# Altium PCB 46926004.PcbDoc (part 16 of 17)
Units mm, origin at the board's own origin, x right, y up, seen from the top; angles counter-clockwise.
Board outline 250 x 200 mm, 6 copper layers (Top Layer, INT1_GND, INT2_SIG, INT3_SIG, INT4_GND, Bottom Layer), stack 1.71 mm thick; 1450 components, 1293 nets, 5656 pads, 2307 vias.
Unrouted connection lines stored in the file: 2.
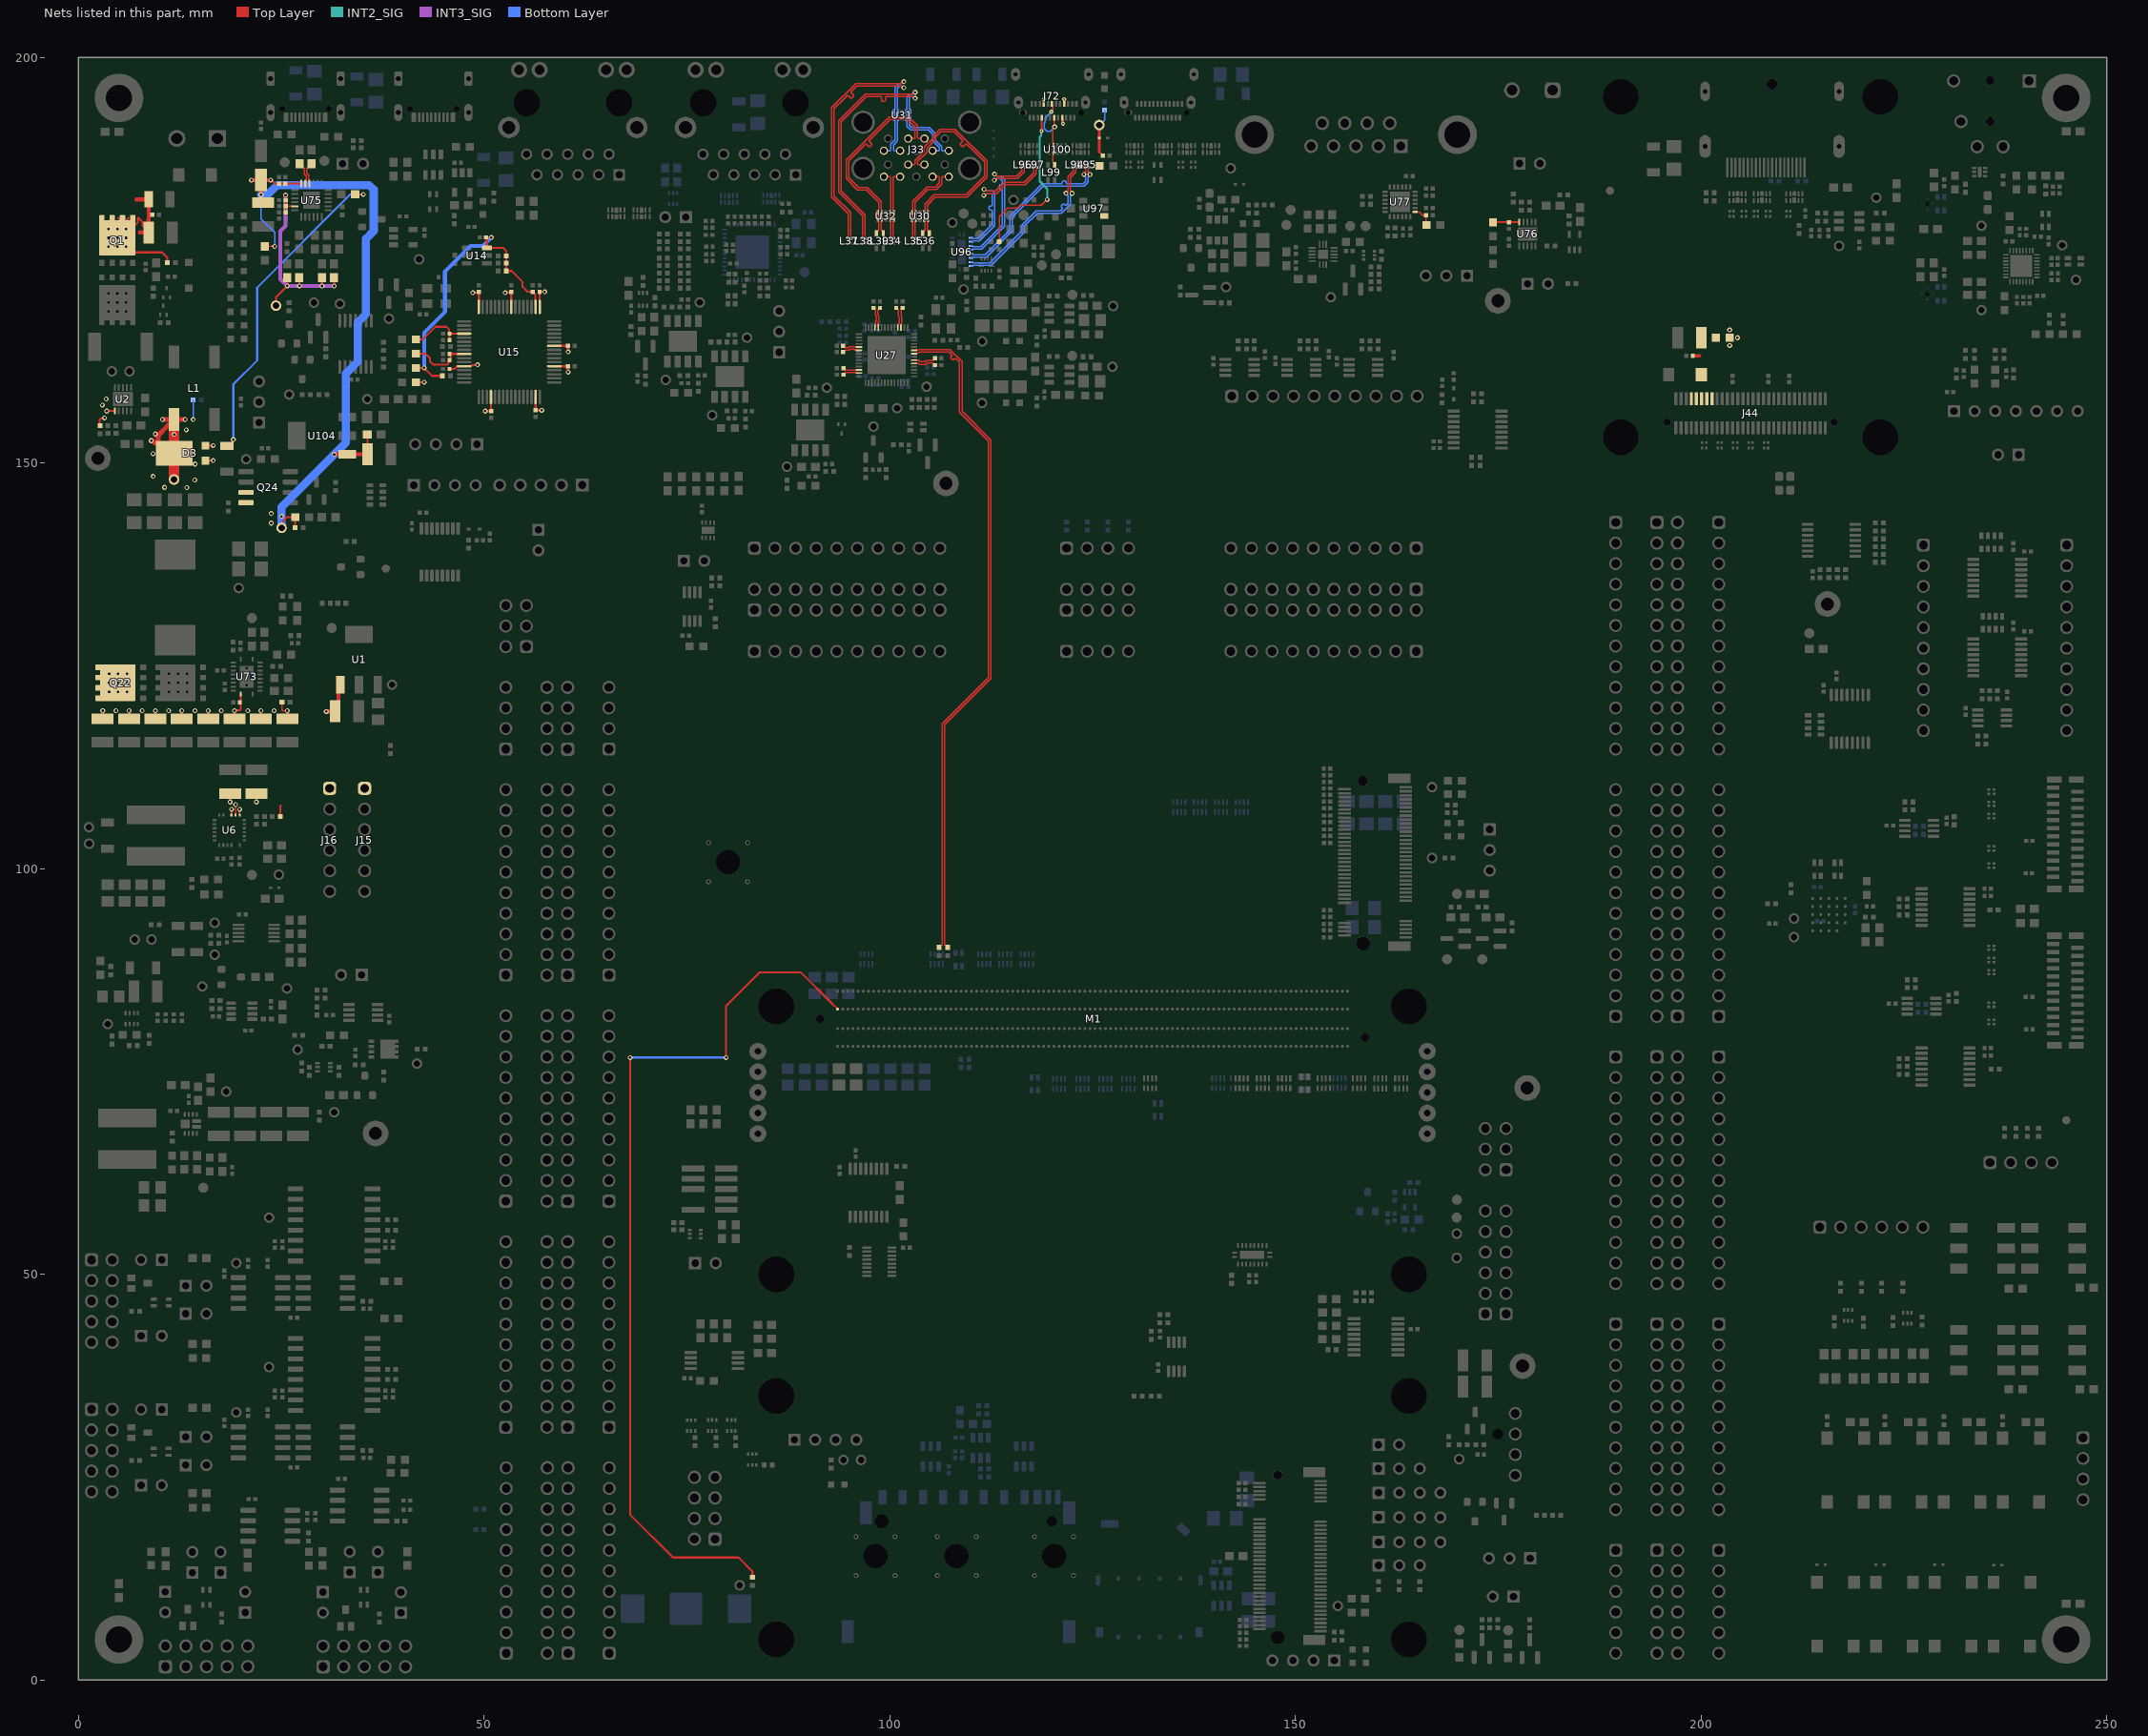
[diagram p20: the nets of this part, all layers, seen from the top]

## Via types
v1: diameter 0.6, hole 0.3, Top Layer to Bottom Layer, tented both sides, 2171 vias
v2: diameter 0.6, hole 0.3, Top Layer to Bottom Layer, 48 vias
v3: diameter 1, hole 0.5, Top Layer to Bottom Layer, tented both sides, 37 vias
v4: diameter 0.5, hole 0.2, Top Layer to Bottom Layer, tented both sides, 34 vias
v5: diameter 0.6, hole 0.3, Top Layer to Bottom Layer, tented bottom, 17 vias

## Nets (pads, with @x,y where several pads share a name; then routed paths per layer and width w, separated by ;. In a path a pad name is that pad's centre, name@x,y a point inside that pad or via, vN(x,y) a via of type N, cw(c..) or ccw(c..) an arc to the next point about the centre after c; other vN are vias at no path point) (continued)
USB_3_P: J72.A6 J72.B6 L99.1 U100.4 U100.7 | length 11.4
  Top Layer w0.15: v4(119.917,193.3) 119.917,193.362 120.117,193.563 120.117,193.87 120.075,193.912 120.075,194.175 J72.B6@120,194.25 ; J72.A6@120.25,192.55 120.25,191.527 v1(120.332,191.445) 120.332,191.357 120.107,191.132 120.107,190.038 120.075,190.006 120.075,189.405 120.175,189.305 120.175,188.93 120.075,188.829 120.075,188.571 120.175,188.471 U100.7@120.175,188.283 120.175,188.096 120.075,187.995 120.075,187.262 120.075,187.138 120.163,187.05 120.225,187.05 120.35,186.925 L99.1@120.35,186.75
  Bottom Layer w0.15: v4(119.917,193.3) 119.183,192.565 119.183,192.075 119.025,191.917 119.025,191.589 119.057,191.556 119.057,191.228 119.365,190.92 119.807,190.92 v1(120.332,191.445)
USB_3_SSRX1_N: L95.1 U96.16 | length 21.4
  Top Layer w0.15: v1(123.93,185.587) 123.93,185.68 124.15,185.9 124.15,186.287 124.125,186.312 124.125,186.4 L95.1@124.05,186.475
  Bottom Layer w0.15: U96.16@110.01,175.775 110.19,175.775 110.29,175.675 111.775,175.675 114.821,178.722 114.821,180.437 118.806,184.422 121.076,184.422 121.151,184.422 121.251,184.522 121.251,184.69 121.351,184.79 121.651,184.79 121.751,184.69 121.751,184.522 121.851,184.422 122.627,184.422 123.827,184.422 124.153,184.748 124.153,185.274 123.93,185.497 v1(123.93,185.587)
USB_3_SSRX1_P: L95.2 U96.17 | length 21.4
  Top Layer w0.15: L95.2@124.55,186.475 124.475,186.4 124.475,186.312 124.45,186.287 124.45,185.895 124.68,185.665 v1(124.68,185.575)
  Bottom Layer w0.15: U96.17@110.01,175.275 110.19,175.275 110.29,175.375 111.899,175.375 115.121,178.597 115.121,180.313 118.93,184.122 123.951,184.122 124.453,184.624 124.453,185.262 124.68,185.489 v1(124.68,185.575)
USB_3_SSRX2_N: L97.2 U96.12 | length 17.2
  Top Layer w0.15: v1(111.6,183) 111.69,183 111.913,183.223 113.181,183.223 114.259,184.301 116.714,184.301 118.05,185.637 118.05,186.287 118.075,186.312 118.075,186.4 L97.2@118.15,186.475
  Bottom Layer w0.15: U96.12@110.01,177.775 110.19,177.775 110.275,177.69 110.898,177.69 112.616,179.407 112.616,180.997 112.616,181.072 112.516,181.172 112.311,181.172 112.211,181.272 112.211,181.572 112.311,181.672 112.516,181.672 112.616,181.772 112.616,182.03 112.616,183.122 112.528,183.21 111.913,183.21 111.703,183 v1(111.6,183)
USB_3_SSRX2_P: L97.1 U96.13 | length 17.2
  Top Layer w0.15: v1(111.612,183.75) 111.698,183.75 111.925,183.523 113.057,183.523 114.135,184.601 116.59,184.601 117.75,185.761 117.75,186.287 117.725,186.312 117.725,186.4 L97.1@117.65,186.475
  Bottom Layer w0.15: U96.13@110.01,177.275 110.19,177.275 110.275,177.36 111.035,177.36 112.946,179.271 112.946,183.259 112.664,183.54 111.925,183.54 111.715,183.75 v1(111.612,183.75)
USB_3_SSTX1_N: L94.1 U96.18 | length 21.3
  Top Layer w0.15: v1(121.723,183.271) 121.723,183.359 121.948,183.584 121.948,185.305 122.625,185.982 122.625,186.287 122.6,186.312 122.6,186.4 L94.1@122.525,186.475
  Bottom Layer w0.15: U96.18@110.01,174.775 110.19,174.775 110.29,174.675 112.361,174.675 116.273,178.587 116.273,179.307 118.067,181.1 121.041,181.1 121.192,181.251 121.245,181.304 121.245,181.446 121.126,181.565 121.126,181.706 121.338,181.918 121.479,181.918 121.599,181.799 121.74,181.799 121.821,181.88 121.946,182.005 121.946,182.958 121.723,183.181 v1(121.723,183.271) 121.723,183.168 121.933,182.958
USB_3_SSTX1_P: L94.2 U96.19 | length 21.3
  Top Layer w0.15: v1(122.473,183.259) 122.473,183.347 122.248,183.572 122.248,185.181 122.925,185.858 122.925,186.287 122.95,186.312 122.95,186.4 L94.2@123.025,186.475
  Bottom Layer w0.15: U96.19@110.01,174.275 110.19,174.275 110.29,174.375 112.486,174.375 116.573,178.463 116.573,179.183 118.191,180.8 121.165,180.8 122.246,181.881 122.246,182.946 122.473,183.173 v1(122.473,183.259) 122.473,183.156 122.263,182.946
USB_3_SSTX2_N: L96.2 U96.14 | length 16.8
  Top Layer w0.15: v1(112.89,184.87) 112.98,184.87 113.203,185.093 115.742,185.093 116.55,185.901 116.55,186.287 116.575,186.312 116.575,186.4 L96.2@116.65,186.475
  Bottom Layer w0.15: U96.14@110.01,176.775 110.19,176.775 110.29,176.675 111.203,176.675 113.842,179.314 113.842,183.63 113.842,183.705 113.742,183.805 113.587,183.805 113.487,183.905 113.487,184.205 113.587,184.305 113.742,184.305 113.842,184.405 113.842,184.69 113.842,184.8 113.55,185.093 113.203,185.093 112.98,184.87 v1(112.89,184.87)
USB_3_SSTX2_P: L96.1 U96.15 | length 16.8
  Top Layer w0.15: v1(112.902,185.62) 112.988,185.62 113.215,185.393 115.618,185.393 116.25,186.025 116.25,186.287 116.225,186.312 116.225,186.4 L96.1@116.15,186.475
  Bottom Layer w0.15: U96.15@110.01,176.275 110.19,176.275 110.29,176.375 111.327,176.375 114.142,179.19 114.142,184.924 113.674,185.393 113.215,185.393 112.988,185.62 v1(112.902,185.62)
USB_3_VBUS: C35.2 C328.2 D36.2 J72.A4 J72.A9 J72.B4 J72.B9 R389.2 R396.2 U97.1 X107.1 | length 28.5
  Top Layer w0.15: R389.2@113.495,177.305 113.495,180.373 114.039,180.918 114.537,181.416 115.719,181.416 116.085,181.782 118.699,181.782 v1(119.4,182.483) ; 125.825,188.36 C328.2@126.285,187.9
  Top Layer w0.25: v4(118.701,190.913) 118.725,190.938 118.725,192.525 J72.A9@118.75,192.55 ; J72.A4@121.25,192.55 121.275,192.525 121.275,191.959 121.35,191.884 v4(121.35,191.817)
  Top Layer w0.3: J72.B4@119,194.25 v4(119,194.85) ; J72.B9@121.5,194.25 v4(121.5,194.85)
  Top Layer w0.4: 125.825,188.36 X107.1@125.825,191.662
  INT2_SIG w0.25: v4(118.701,190.913) 118.653,190.866 118.653,190.347 118.47,190.163 118.47,184.746 119.4,183.815 v1(119.4,182.483)
  Bottom Layer w0.15: X107.1@125.825,191.662 126.482,192.319 R396.2@126.482,193.5
USB_4_N: J33.U2 L36.4 U30.4 U30.7 | length 28.4
  Top Layer w0.15: L36.4@104.05,178.275 104.05,178.45 104.325,178.725 104.325,179.371 104.325,179.746 104.225,179.846 U30.4@104.225,180.033 104.225,180.221 104.325,180.321 104.325,180.579 104.225,180.679 U30.7@104.225,180.867 104.225,181.054 104.325,181.154 104.325,181.924 105.476,183.075 109.375,183.075 111.675,185.375 111.675,187.111 110.253,188.533 109.487,189.298 109.346,189.298 109.053,189.006 108.912,189.006 108.7,189.218 108.7,189.359 108.993,189.652 108.993,189.793 108.586,190.2 107.936,190.85 106.275,190.85 105.625,190.2 105.625,189.87 104.555,188.8 104.555,188.325 103.43,187.2 103.43,186.888 103.518,186.8 J33.U2@104.28,186.8
USB_4_P: J33.U3 L36.1 U30.5 U30.6 | length 28.4
  Top Layer w0.15: J33.U3@102.28,186.8 103.042,186.8 103.13,186.888 103.13,187.325 104.255,188.45 104.255,188.925 105.325,189.995 105.325,190.324 106.151,191.15 108.06,191.15 111.975,187.235 111.975,185.25 109.499,182.775 105.6,182.775 104.625,181.8 104.625,181.155 104.725,181.054 U30.6@104.725,180.867 104.725,180.679 104.625,180.579 104.625,180.321 104.725,180.221 U30.5@104.725,180.033 104.725,179.846 104.625,179.745 104.625,179.495 104.625,178.725 104.9,178.45 L36.1@104.9,178.275
USB_4_SSRX_N: J33.U5 L34.2 U32.2 U32.9 | length 8.6
  Top Layer w0.15: J33.U5@99.28,185.3 100.042,185.3 100.13,185.212 100.13,181.171 100.03,181.071 U32.2@100.03,180.884 100.03,180.696 100.13,180.596 100.13,180.338 100.03,180.238 U32.9@100.03,180.05 100.03,179.863 100.13,179.763 100.13,177.913 100.105,177.888 100.105,177.8 L34.2@100.03,177.725
USB_4_SSRX_P: J33.U6 L34.1 U32.1 U32.10 | length 8.6
  Top Layer w0.15: L34.1@100.53,177.725 100.455,177.8 100.455,177.888 100.43,177.913 100.43,179.763 100.53,179.863 U32.10@100.53,180.05 100.53,180.238 100.43,180.338 100.43,180.596 100.53,180.696 U32.1@100.53,180.884 100.53,181.071 100.43,181.171 100.43,182.1 100.43,185.212 100.518,185.3 J33.U6@101.28,185.3
USB_4_SSTX_N: J33.U8 L35.2 U30.1 U30.10 | length 10.6
  Top Layer w0.15: L35.2@102.725,177.725 102.8,177.8 102.8,177.888 102.825,177.913 102.825,179.746 102.725,179.846 U30.1@102.725,180.033 102.725,180.221 102.825,180.321 102.825,180.579 102.737,180.667 U30.10@102.737,181.067 ; U30.10@102.725,181.054 102.825,181.154 102.825,182.243 104.582,184 105.613,184 106.13,184.517 106.13,185.212 106.042,185.3 J33.U8@105.28,185.3
USB_4_SSTX_P: J33.U9 L35.1 U30.2 U30.9 | length 10.6
  Top Layer w0.15: L35.1@103.225,177.725 103.15,177.8 103.15,177.888 103.125,177.913 103.125,179.746 103.225,179.846 U30.2@103.225,180.033 103.225,180.221 103.125,180.321 103.125,180.579 103.225,180.679 U30.9@103.225,180.867 103.225,181.054 103.125,181.154 103.125,182.119 104.706,183.7 105.737,183.7 106.43,184.393 106.43,185.212 106.518,185.3 J33.U9@107.28,185.3
USB_5_N: J33.L2 L39.4 U32.5 U32.6 | length 25.5
  Top Layer w0.15: L39.4@98.355,178.325 98.355,178.5 98.48,178.625 98.542,178.625 98.63,178.713 98.63,179.388 ; 98.63,179.388 98.63,179.763 98.53,179.863 U32.6@98.53,180.05 98.53,180.238 98.63,180.338 98.63,180.596 98.53,180.696 U32.5@98.53,180.884 98.53,181.071 98.63,181.171 98.63,181.546 ; 98.63,181.546 98.63,182.133 97.096,183.667 96.034,183.667 94.625,185.076 94.625,187.349 99.951,192.675 102.324,192.675 103.43,191.569 103.43,190.088 103.518,190 J33.L2@104.28,190
USB_5_P: J33.L3 L39.1 U32.4 U32.7 | length 25.5
  Top Layer w0.15: L39.1@99.205,178.325 99.205,178.5 99.08,178.625 99.018,178.625 98.93,178.713 98.93,179.512 98.93,179.762 99.03,179.863 U32.7@99.03,180.05 99.03,180.238 98.93,180.338 98.93,180.596 99.03,180.696 U32.4@99.03,180.884 99.03,181.071 98.93,181.172 98.93,181.422 98.93,182.257 97.22,183.967 96.158,183.967 94.925,185.2 94.925,187.225 96.597,188.897 97.003,189.303 97.145,189.303 97.438,189.011 97.579,189.011 97.791,189.223 97.791,189.364 97.498,189.657 97.498,189.798 97.992,190.292 100.075,192.375 102.2,192.375 103.13,191.445 103.13,190.088 103.042,190 J33.L3@102.28,190
USB_5_SSRX_N: J33.L5 L37.2 U31.1 U31.10 | length 38
  Top Layer w0.15: L37.2@94.775,177.725 94.85,177.8 94.85,177.888 94.875,177.913 94.875,180.75 92.85,182.775 92.85,193.814 95.826,196.79 101.437,196.79 101.662,197.015 v1(101.75,197.015)
  Bottom Layer w0.15: J33.L5@99.28,188.5 100.046,188.5 100.134,188.588 100.134,189.328 100.625,189.82 100.625,192.204 100.525,192.304 U31.10@100.525,192.491 100.525,192.679 100.625,192.779 100.625,193.038 100.525,193.138 U31.1@100.525,193.325 100.525,193.513 100.625,193.613 100.625,196.307 101.108,196.79 101.437,196.79 101.662,197.015 v1(101.75,197.015) 101.647,197.015 101.437,196.805
USB_5_SSRX_P: J33.L6 L37.1 U31.2 U31.9 | length 37.9
  Top Layer w0.15: L37.1@95.275,177.725 95.2,177.8 95.2,177.888 95.175,177.913 95.175,180.874 93.15,182.899 93.15,193.69 94.354,194.894 94.76,195.3 94.902,195.3 95.197,195.005 95.338,195.005 95.55,195.217 95.55,195.359 95.255,195.654 95.255,195.795 95.837,196.377 95.95,196.49 101.437,196.49 101.662,196.265 v1(101.75,196.265)
  Bottom Layer w0.15: U31.9@100.975,192.491 100.975,192.729 100.925,192.779 100.925,193.038 101.025,193.138 U31.2@101.025,193.325 101.025,193.513 100.925,193.613 100.925,196.182 101.233,196.49 101.437,196.49 101.662,196.265 v1(101.75,196.265) 101.647,196.265 101.437,196.475 ; U31.9@101.025,192.491 101.025,192.304 100.925,192.204 100.925,189.695 100.445,189.215 100.445,188.605 100.55,188.5 J33.L6@101.28,188.5
USB_5_SSTX_N: J33.L8 L38.2 U31.4 U31.7 | length 39
  Top Layer w0.15: L38.2@96.55,177.725 96.625,177.8 96.625,177.888 96.65,177.913 96.65,180.475 93.7,183.425 93.7,192.206 96.984,195.49 102.812,195.49 103.037,195.715 v1(103.125,195.715)
  Bottom Layer w0.15: U31.7@102.11,192.764 U31.7@102.025,192.679 ; 102.546,191.075 102.443,191.178 ; 102.812,195.505 103.022,195.715 v1(103.125,195.715) 103.037,195.715 102.812,195.49 102.483,195.49 102.125,195.132 102.125,193.613 102.025,193.513 U31.4@102.025,193.325 102.025,193.138 102.125,193.038 102.125,192.779 U31.7@102.025,192.679 ; J33.L8@105.28,188.5 106.022,188.5 106.11,188.588 106.11,188.912 105.29,189.731 105.29,190.531 104.731,191.09 102.531,191.09 102.443,191.178 ; U31.7@102.025,192.679 U31.7@102.025,192.491 102.025,192.304 102.125,192.204 102.125,191.496 102.443,191.178
USB_5_SSTX_P: J33.L9 L38.1 U31.5 U31.6 | length 38.8
  Top Layer w0.15: L38.1@97.05,177.725 96.975,177.8 96.975,177.888 96.95,177.913 96.95,180.599 94,183.549 94,192.082 97.108,195.19 98.299,195.19 98.874,195.19 98.974,195.09 98.974,194.668 99.074,194.568 99.374,194.568 99.474,194.668 99.474,195.09 99.574,195.19 100.38,195.19 102.812,195.19 103.037,194.965 v1(103.125,194.965)
  Bottom Layer w0.15: 102.812,195.175 103.022,194.965 v1(103.125,194.965) 103.037,194.965 102.812,195.19 102.608,195.19 102.425,195.008 102.425,193.613 102.525,193.513 U31.5@102.525,193.325 102.525,193.138 102.425,193.037 102.425,192.779 102.525,192.679 U31.6@102.525,192.491 102.525,192.304 102.425,192.203 102.425,191.65 102.685,191.39 104.855,191.39 105.59,190.655 105.59,189.856 106.41,189.036 106.41,188.588 106.498,188.5 J33.L9@107.28,188.5
USB__2__SSRX_N: C120.2 U27.48 | length 2.8
  Top Layer w0.15: U27.48@102.995,162.693 103.022,162.666 103.547,162.666 103.723,162.49 104.329,162.49 104.483,162.644 105.272,162.644 C120.2@105.567,162.939
USB__2__SSRX_P: C117.2 U27.47 | length 2.8
  Top Layer w0.15: U27.47@102.995,162.293 103.022,162.266 103.523,162.266 103.598,162.19 104.454,162.19 104.607,162.344 105.299,162.344 C117.2@105.567,162.075
USB__2__SSTX_N: R462.2 U27.51 | length 82.8
  Top Layer w0.15: U27.51@102.995,163.893 103.01,163.907 103.461,163.907 103.553,164 107.42,164 108.902,162.518 108.902,156.389 112.45,152.84 112.45,123.45 106.76,117.76 106.76,90.613 106.848,90.525 106.91,90.525 R462.2@107.135,90.3
USB__2__SSTX_P: R461.2 U27.50 | length 82.8
  Top Layer w0.15: U27.50@102.995,163.493 103.297,163.493 103.37,163.566 103.543,163.566 103.677,163.7 107.218,163.7 107.296,163.7 107.663,163.332 107.663,163.191 107.546,163.074 107.546,162.932 107.758,162.72 107.9,162.72 108.017,162.837 108.158,162.837 108.502,162.493 108.602,162.394 108.602,156.264 112.15,152.716 112.15,123.574 106.46,117.885 106.46,90.613 106.373,90.525 106.31,90.525 R461.2@106.085,90.3
USB__3__SSTX_N: C131.2 U27.4 | length 2.7
  Top Layer w0.15: C131.2@100.792,169.125 101.082,168.835 101.082,168.062 101.194,167.95 101.194,167.312 101.167,167.285 101.167,167.278 101.067,167.178 101.067,167.069 100.994,166.996 U27.4@100.994,166.694
USB__3__SSTX_P: C135.2 U27.3 | length 2.6
  Top Layer w0.15: U27.3@101.394,166.694 101.421,166.721 101.421,167.107 101.467,167.153 101.467,167.161 101.494,167.188 101.494,168.074 101.382,168.186 101.382,168.772 101.382,168.94 C135.2@101.567,169.125
USB__4__SSTX_N: C132.2 U27.11 | length 2.7
  Top Layer w0.15: C132.2@97.992,169.125 98.242,168.875 98.242,168.227 98.36,168.109 98.36,167.563 98.244,167.447 98.244,167.1 98.221,167.077 98.221,166.721 U27.11@98.194,166.694
USB__4__SSTX_P: C136.2 U27.10 | length 2.7
  Top Layer w0.15: U27.10@98.594,166.694 98.567,166.721 98.567,167.077 98.544,167.1 98.544,167.323 98.66,167.439 98.66,168.233 98.542,168.351 98.542,168.875 C136.2@98.792,169.125
USB__5__SSTX_N: C133.2 U27.20 | length 2.1
  Top Layer w0.15: C133.2@94.367,163.7 94.367,163.8 94.452,163.885 94.517,163.885 94.54,163.908 95.008,163.908 95.118,164.018 95.619,164.018 95.721,163.915 96.17,163.915 U27.20@96.193,163.893
USB__5__SSTX_P: C137.2 U27.19 | length 2
  Top Layer w0.15: C137.2@94.367,164.45 94.367,164.35 94.452,164.265 94.517,164.265 94.54,164.242 94.869,164.242 94.979,164.352 95.73,164.352 95.762,164.32 96.166,164.32 U27.19@96.193,164.293
USB__6__SSTX_N: C134.2 U27.27 | length 2
  Top Layer w0.15: C134.2@94.292,160.897 94.542,161.147 95.358,161.147 95.363,161.143 95.787,161.143 95.81,161.12 96.166,161.12 U27.27@96.193,161.093
USB__6__SSTX_P: C138.2 U27.26 | length 2
  Top Layer w0.15: C138.2@94.292,161.697 94.542,161.447 95.483,161.447 95.487,161.443 95.787,161.443 95.81,161.466 96.166,161.466 U27.26@96.193,161.493
USB_CYP_N: R321.1 U75.16 | length 2.9
  Top Layer w0.15: U75.16@28.475,184.45 28.475,184.775 28.375,184.875 28.375,185.475 28.15,185.7 28.15,186.337 28.238,186.425 28.325,186.425 28.75,186.85 R321.1@28.75,186.9
USB_CYP_P: R320.1 U75.17 | length 2.9
  Top Layer w0.15: R320.1@27.25,186.9 27.25,186.85 27.675,186.425 27.762,186.425 27.85,186.337 27.85,185.576 28.075,185.351 28.075,184.875 27.975,184.775 U75.17@27.975,184.45
V232: C306.1 L79.2 U77.19 | length 2.8
  Top Layer w0.15: U77.19@164.725,180.95 U77.19@164.915,180.95 165.243,180.95 165.31,180.884 165.643,180.55 C306.1@166.1,180.55 166.1,179.425 L79.2@166.175,179.35
V485: C308.1 L80.2 U76.10 | length 3.2
  Top Layer w0.25: L80.2@174.373,179.65 174.402,179.679 C308.1@176.3,179.679 U76.10@177.6,179.679
V+: C2.2 C3.1 F1.2 Q1.5 Q1.6 Q1.7 Q1.8 R5.2 R351.2 U2.1 | length 22.4
  Top Layer w0.25: R5.2@2.676,154.627 2.604,154.699 2.604,155.356 2.751,155.503 3.142,155.503 v1(3.209,155.57) ; U2.1@4.475,156.445 4.477,156.443 U2.1@4.477,156.438 ; 4.89,180.23 4.89,180.192 5.538,179.544 5.538,179.217 5.605,179.15 5.672,179.217 5.672,179.681 6.16,180.169 6.16,180.23 ; Q1.8@5.995,176.76 6.78,175.975 10.32,175.975 10.95,175.345 R351.2@10.95,174.72 ; Q1.8@6.8,179.15 7.333,179.683 7.333,180.133 7.43,180.23 ; 7.43,180.192 7.43,180.169 7.928,179.671 7.928,179.217 7.995,179.15 8.515,179.67 8.515,180.045 8.673,180.203 8.7,180.23
  Top Layer w0.254: v1(3.5,156.4) 3.545,156.445 4.142,156.445 ; 3.809,156.445 4.142,156.445 ; U2.1@4.475,156.445 4.142,156.445
  Top Layer w0.5: 7.15,182.5 F1.2@8.673,182.5 8.673,180.203 C2.2@8.673,178.427 ; 7.55,178.45 8.65,178.45 C2.2@8.673,178.427 ; C2.2@8.675,178.425 C2.2@8.673,178.427
  other v1: 2.95,157.15 3.425,157.9
V_BUS_PD: C284.2 C293.2 C296.2 C297.2 C299.1 L77.2 Q24.7 Q24.8 R315.2 R325.1 R332.2 U75.18 U104.1 X94.1 | length 87.9
  Top Layer w0.15: R315.2@22.995,176.703 v1(24.192,176.703)
  Top Layer w0.25: L77.2@22.5,184.89 L77.2@22.51,184.88 ; v1(23.7,184.875) 23.795,184.875 24.22,184.45 C297.2@24.725,184.45 C296.2@25.525,184.45 U75.18@27.475,184.45 ; X94.1@25.045,142.015 25.246,142.216 25.246,142.891 25.685,143.33 C299.1@26.71,143.33 R332.2@26.71,142.03 ; C284.2@35.625,151.075 R325.1@35.625,153.566
  Top Layer w0.5: v1(21.32,184.88) 22.51,184.88 22.5,184.87 v1(22.5,183.08) ; L77.2@22.51,184.875 v1(23.7,184.875) ; v1(31.525,151.075) U104.1@33.125,151.075 C284.2@35.625,151.075
  Bottom Layer w0.15: v1@22.5,183.075 22.5,180.1 24.192,178.408 v1(24.192,176.703)
  Bottom Layer w1: v1@22.5,183.075 23.309,183.075 24.514,184.28 35.814,184.28 36.4,183.694 36.4,178.603 35.45,177.653 35.45,168.36 34.45,167.36 34.45,162.528 32.974,161.051 32.974,152.524 25.045,144.595 X94.1@25.045,142.015
  other v1: 23.765,142.6 25.045,143.434 23.765,143.795
VCC_BACKUP: M1.B100 R227.2 | length 110.7
  Top Layer w0.15: 92.973,83.291 92.976,83.291 M1.B100@93.567,82.7
  Top Layer w0.25: v1(68,76.726) 68,20.4 73.3,15.1 81.356,15.1 83.085,13.37 R227.2@83.085,12.521 ; v1(79.825,76.726) 79.825,83.094 83.931,87.2 89.064,87.2 92.973,83.291
  Bottom Layer w0.25: v1(68,76.726) v1(79.825,76.726)
VCC_FT: C85.2 C87.2 C88.2 C89.2 L19.2 U15.20 U15.31 U15.42 U15.56 | length 10.8
  Top Layer w0.25: L19.2@41.615,159.975 v1(42.615,159.975) ; v1(50.14,156.4) C85.2@50.865,156.4 50.865,157.371 50.86,157.377 50.86,158.13 U15.20@50.865,158.135 ; v1(52.6,170.99) 52.655,171.045 53.285,171.045 C89.2@53.34,171.1 ; U15.56@53.35,169.25 C89.2@53.35,170.99
  Top Layer w0.3: U15.31@56.35,158.15 56.35,156.515 C87.2@56.365,156.5 v1(57.115,156.5) ; U15.42@58.65,164.45 C88.2@60.35,164.45 v1(60.35,163.7)
VCORE_FT: C82.2 C83.2 C84.2 C86.2 U15.12 U15.37 U15.49 U15.64 | length 11.1
  Top Layer w0.15: C86.2@49.34,171 C86.2@49.35,170.99 ; U15.64@49.345,169.245 U15.64@49.35,169.25
  Top Layer w0.25: C83.2@45.74,161.6 46.349,161.6 46.611,161.862 46.688,161.862 46.701,161.875 46.711,161.875 46.786,161.95 U15.12@47.55,161.95 47.56,161.96 48.432,161.96 48.531,162.058 49.125,162.058 v1(49.192,162.125) ; v1(48.6,170.99) 49.35,170.99 U15.64@49.35,169.25 ; U15.49@56.85,169.25 C82.2@56.85,171.1 v1(57.475,171.1)
  Top Layer w0.3: U15.37@58.65,161.95 C84.2@60.35,161.95 v1(60.35,161.2)
VDDD_3V3: C292.2 C294.2 C295.2 R328.2 R329.1 R337.2 R388.1 U75.23 X93.1 | length 28
  Top Layer w0.15: C295.2@25.55,180.9 C294.2@25.55,181.65 C292.2@25.55,182.4 ; C294.2@25.65,181.65 U75.23@26.675,181.65
  Top Layer w0.25: X93.1@24.35,169.4 24.35,170.429 v1(25.75,171.829) 25.75,172.818 R388.1@25.72,172.848 ; v1(25.532,183.038) 25.541,183.029 25.541,182.509 C292.2@25.65,182.4 ; R337.2@27.22,172.848 27.25,172.818 v1(27.25,171.829) ; R329.1@29.995,172.845 30.025,172.815 v1(30.025,171.826) ; R328.2@31.495,172.844 31.525,172.814 v1(31.525,171.825)
  INT3_SIG w0.5: v1(25.532,183.038) 25.532,179.232 24.892,178.592 24.892,172.684 25.75,171.826 26.325,171.826 ; 26.325,171.826 v1(31.525,171.825)
VIN: C1.2 C20.2 C23.2 C265.2 C266.2 C270.1 C272.2 C273.2 C274.2 C275.2 C278.2 C281.2 D3.3 J15.1 J16.1 L1.3 L55.2 Q22.5 Q22.6 Q22.7 Q22.8 R10.1 R35.2 R307.2 U1.1 U6.7 U6.8 U6.9 U73.20 X3.1 | length 51.7
  Top Layer w0.15: Q22.8@2.422,121.015 2.627,121.22 2.992,121.22 Q22.8@3.502,121.73 ; Q22.7@2.422,122.285 2.46,122.285 3.014,122.839 3.416,122.839 Q22.8@3.502,122.925 ; Q22.6@2.422,123.555 2.937,123.555 3.502,124.12 3.002,124.62 2.627,124.62 Q22.5@2.422,124.825 ; L1.3@11.79,155.372 L1.3@11.794,155.368 ; v1(18.7,108.225) C20.2@18.7,109.275 ; U6.9@18.87,106.627 v1(18.87,107.335) ; U6.8@19.37,106.627 v1@19.37,107.9 ; U6.7@19.871,106.627 v1(19.871,107.335) ; R307.2@25.092,120.525 25.092,119.603 25.22,119.475 v1(25.742,119.475)
  Top Layer w0.25: C278.2@2.992,118.475 v1(2.992,119.475) ; C281.2@6.242,118.475 v1(6.242,119.475) ; C275.2@9.492,118.475 v1(9.492,119.475) ; C274.2@12.742,118.475 v1(12.742,119.475) ; C273.2@15.992,118.475 v1(15.992,119.475) ; v1@19.156,119.561 v1(19.242,119.475) ; C272.2@19.242,118.475 v1(19.242,119.475) ; U73.20@19.992,121.525 19.992,120.5 19.992,119.652 19.882,119.542 19.309,119.542 v1(19.242,119.475) ; C266.2@22.492,118.475 v1(22.492,119.475) ; R35.2@24.9,106.45 24.9,107.729 24.946,107.775 ; C265.2@25.742,118.475 v1(25.742,119.475)
  Top Layer w0.5: v1(30.55,119.375) 31.6,119.375 32.05,119.825 32.05,122.425 U1.1@32.3,122.675
  Top Layer w0.6: v1(8.967,152.762) v1@9.114,152.762 ; 9.353,152.523 9.85,152.523 D3.3@9.85,152.446 ; D3.3@10.277,152.02 D3.3@9.85,152.446 ; D3.3@10.315,152.058 11.15,151.222 D3.3@11.798,151.222 11.074,151.222 D3.3@9.85,152.446 ; v1(10.362,155.372) L1.3@11.779,155.372 ; v1(11.79,153.541) L1.3@11.79,155.383 ; v1(13.148,155.372) L1.3@11.779,155.372 ; D3.3@9.85,152.446 9.85,153.203 9.73,153.323 11.048,154.641 11.45,154.641 11.779,154.97 L1.3@11.779,155.372
  Top Layer w1.3: X3.1@11.794,147.972 L1.3@11.794,155.368
  Bottom Layer w0.15: v1(14.14,155.36) 14.14,157.77 R10.1@14.145,157.775
  other v1: 19.366,107.9 21.925,108.225 4.617,119.475 7.867,119.475 11.117,119.475 14.367,119.475 17.617,119.475 20.867,119.475 24.117,119.475 13.35,146.975 10.625,147 14.36,147.915 9.2,148.37 14.38,149.88 9.196,151.148 9.486,153.589 13.3,154.1 203.522,164.497 204.475,165.45 203.522,166.403
VIN_DSI: C205.2 C208.2 D31.2 J44.7 J44.9 J44.11 J44.13 J44.15 L55.1 | length 0.9
  Top Layer w0.4: C208.2@198.972,163.2 199.851,163.2
VPD: D3.1 D3.2 F2.2 R339.1 | length 42
  Top Layer w0.25: D3.1@15.684,150.302 15.689,150.307 v1(16.609,150.307) ; D3.2@15.689,152.137 15.699,152.147 v1(16.609,152.147) ; F2.2@18.305,152.13 18.605,152.13 18.975,152.5 18.975,152.667 19.1,152.792 v1(19.1,152.887) ; R339.1@34.11,183.15 34.135,183.125 v1(35.125,183.125)
  Bottom Layer w0.25: v1(19.1,152.887) 19.1,159.715 22.035,162.65 22.035,171.635 33.525,183.125 v1(35.125,183.125)
VPHY_FT: C76.2 C80.2 L16.2 U15.4 | length 7.9
  Top Layer w0.25: L16.2@41.615,165.225 42.44,165.225 44.015,166.8 45.34,166.8 45.701,166.439 45.701,166.085 C80.2@45.753,166.034 ; C76.2@45.74,165.175 C80.2@45.74,165.95 ; C80.2@45.756,166.034 45.84,165.95 U15.4@47.55,165.95
VPLL_FT: C75.2 C79.2 L18.2 U15.9 | length 7.9
  Top Layer w0.25: L18.2@41.615,163.475 42.79,163.475 43.34,162.925 43.34,162.525 43.715,162.15 45.45,162.15 45.605,162.305 45.605,162.565 C75.2@45.74,162.7 45.84,162.7 C79.2@45.84,163.45 ; C79.2@45.84,163.475 45.865,163.45 U15.9@47.55,163.45
VREG_FT: C74.2 C78.2 L17.2 R86.1 R87.1 R89.1 R90.1 U14.6 U15.50 | length 37.6
  Top Layer w0.25: L17.2@41.615,161.725 v1(42.615,161.725) 43.59,160.75 R90.1@44.84,160.75 ; v1(50.9,177.811) 50.895,177.816 50.35,177.816 50.355,177.811 U14.6@50.355,176.516 52.383,176.516 52.74,176.159 R86.1@52.74,175.55 R87.1@52.74,174.625 R89.1@52.74,173.675 53.403,173.675 54.744,172.334 54.744,171.741 55.374,171.111 55.989,171.111 55.989,171.089 56.011,171.089 56.135,170.965 56.135,170.942 56.33,170.748 56.33,170.056 56.34,170.045 56.34,169.26 U15.50@56.35,169.25
  Bottom Layer w0.5: v1(42.615,161.725) 42.615,166.065 45.195,168.645 45.195,173.631 48.327,176.763 49.852,176.763 v1(50.9,177.811)
pads on no net: B1.2 B1.4 B2.2 B2.4 B3.2 B3.4 B4.2 B4.4 B5.2 B5.4 B6.2 B6.4 B7.2 B7.4 B8.2 B8.4 D39.2 D39.4 D40.2 D40.4 D41.2 D41.4 D42.2 D42.4 D44.2 FID1.1 FID2.1 FID3.1 FID4.1 FID5.1 FID6.1 J23. J23.A8 J23.B8 J27. J30.0 J30.11 J32.0 J34.0 J34.10 J36.0 J36.10 J39. J39.56 J39.58 J39.59 J39.60 J39.61 J39.62 J39.63 J39.64 J39.65 J39.68 J39.69 J39.75 J39.P1 J39.P2 J42.C4 J42.C6 J42.C8 J43. J43.5 J43.6 J43.7 J43.8 J43.11 J43.13 J43.17 J43.19 J43.20 J43.22 J43.23 J43.24 J43.25 J43.26 J43.28 J43.30 J43.32 J43.34 J43.36 J43.46 J43.48 J43.56 J43.58 J43.67 J43.68 J43.69 J43.SH1 J43.SH2 J44. J44.1 J44.2 J44.5 J44.17 J44.29 J44.41 J44.53 J46. J46.5 J47.3 J56.0 J65. J65.A8 J65.B8 J67.1 J67.4 J67.6 J67.9 J70.MTG J71.MTG J72.0 J72.A8 J72.B8 J77.1 J77.6 J77.7 J77.9 J77.10 J78.1 J78.6 J78.7 J78.9 J78.10 J83.1 J83.6 J83.7 J83.9 J83.10 J84.1 J84.6 J84.7 J84.9 J84.10 M1.1 M1.MH1 M1.MH2 ME1.0 ME2.0 ME3.0 ME4.0 ME5.0 ME6.0 ME7.0 ME8.0 ME9.0 ME10.0 ME11.0 ME12.0 ME13.0 ME13.M0 ME14.0 ME14.M0 ME15.0 ME15.M0 ME18.0 ME18.M0 RA35.1 RA35.4 S1.3 S1.6 S2.3 S2.6 S3.3 S3.6 S4.3 S4.6 U4.3 U5.4 U5.8 U15.16 U15.17 U15.18 U15.19 U15.32 U15.33 U15.34 U15.36 U15.43 U15.44 U15.45 U15.46 U15.55 U15.57 U15.58 U15.59 U15.60 U16.4 U26.1 U26.5 U35.1 U35.5 U36.1 U36.5 U37.20 U37.21 U37.22 U37.23 U37.25 U37.26 U37.29 U37.32 U37.37 U41.1 U41.10 U42.5 U43.7 U45.1 U54.3 U56.A2 U56.A3 U56.B1 U56.B5 U73.7 U73.9 U73.16 U75.7 U75.8 U75.10 U75.20 U75.21 U77.7 U77.8 U77.13 U78.0 U79.0 U80.4 U86.4

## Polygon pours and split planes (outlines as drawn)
NetJ23_A4/B9 on Bottom Layer "NETJ23_A4/B9_L06_P000" (solid, remove dead copper, pour order 0): 40.755,189.04 40.755,191.585 47.041,191.585 47.041,189.506 45.782,188.247 41.548,188.247
5V_T on Bottom Layer "5V_T_L06_P094" (solid, remove dead copper, pour order 94): 95.675,81.875 98.75,78.8 102.539,78.8 105.039,76.3 105.039,74.725 86.675,74.725 83.8,77.6 47.9,77.6 36.948,88.552 16.948,88.552 11.462,94.038 11.462,95.787 12.611,96.936 30.133,96.936 30.665,96.404 48.766,96.404 54.01,91.16 64.05,91.16 84.065,91.16 90,85.225 95.675,85.225
GND on Bottom Layer "GND_L06_P076" (solid, remove dead copper, pour order 76): 229.581,169.025 226.75,169.025 226,169.775 226,182.95 226.675,183.625 230.125,183.625 230.75,183 230.75,170.194
5V on Bottom Layer "5V_L06_P095" (solid, remove dead copper, pour order 95): 7.99,143.537 0.019,143.537 0,143.517 0,86.23 11.755,86.23 12.4,86.875 12.2,87.075 12.2,89.2 4.085,97.315 4.085,137.991 5.43,139.335 7.99,139.335
M2M_3V3 on Bottom Layer "M2M_3V3_L06_P111" (solid, remove dead copper, pour order 111): 155.5,106.9 155.5,105.5 154.485,105.5 153.893,106.093 153.893,112 154.793,112.9 170.5,112.9 172.096,111.304 172.096,108.4 170.596,106.9
V+ on Bottom Layer "V+_L06_P035" (solid, remove dead copper, pour order 35): 4.188,154.783 6.943,157.538 6.943,159.509 9.795,162.36 9.795,178.661 8.606,179.85 0.88,179.85 0.175,179.145 0.175,154.783
NetC289_2 on Bottom Layer "VBUS_CON" (solid, pour order 34): 22,187.3 23.925,187.3 28.905,187.3 30.8,189.195 30.8,193.798 30.044,194.511 29.561,194.511 28.995,193.945 27.33,193.945 26.764,194.511 26.001,194.511 21,189.51 21,188.3
5V_S on Bottom Layer "NONET_L-01_P-001" (solid, remove dead copper, pour order 116): 39.15,78.75 39.843,79.443 40.957,79.443 43.4,77 43.4,25.4 43.253,25.253 42.517,25.253 42.22,25.55 42.22,30.78 41.265,31.735 41.265,74.51 39.15,76.626 39.15,78.741
GND on Bottom Layer "GND_L06_P112" (solid, remove dead copper, pour order 112): 153.493,112.589 153.493,105.917 154.36,105.05 164.8,105.05 165.925,103.925 165.925,95.825 165.365,95.265 162.31,95.265 161.994,95.581 161.994,102.131 160.85,103.275 155.695,103.275 154.72,102.3 152.425,102.3 151.987,102.738 151.987,111.889 152.687,112.589
1V2_UHUB on Bottom Layer "1V2_UHUB_L06_P110" (solid, pour order 110): 102.93,158.23 103.493,158.793 103.493,160.85 104.762,162.12 104.762,166.63 103.293,168.1 96.267,168.1 95.443,167.275 95.443,164.475 94.843,163.875 94.843,160.399 97.012,158.23
GND on Bottom Layer "GND_L06_P022" (solid, pour order 22): 96.674,166.525 102.343,166.525 102.343,160.775 101.517,159.95 101.517,159.1 99.318,159.1 98.893,159.525 97.751,159.525 96.674,160.602
NetC329_2 on Bottom Layer "NONET_L-01_P-001" (solid, remove dead copper, pour order 90): 112.492,194.185 112.492,199.364 113.127,200 125.773,200 125.773,194.161 125.612,194 112.677,194
NetC148_2 on Bottom Layer "C148" (solid, pour order 36): 70.899,190.199 69.85,189.15 67.575,189.15 63.066,193.659 63.066,193.777 60.681,193.777 54.123,187.22 50.009,187.22 49.75,187.479 49.75,195.925 50.425,196.6 67.775,196.6 70.899,193.476
VCC_FT on Bottom Layer "NONET_L-01_P-001" (solid, remove dead copper, pour order 87): 42.29,160.075 42.74,160.525 44.065,160.525 45.64,162.1 45.64,164.875 52.115,171.35 52.638,171.35 53.09,170.898 53.09,170.5 47.89,165.3 47.89,159.8 50.54,157.15 57.265,157.15 60.765,160.65 60.765,161.425 60.04,162.15 60.04,163.775 60.27,164.005 61.06,164.005 61.54,163.525 61.54,159.15 57.74,155.35 49.24,155.35 45.24,159.35 42.59,159.35 42.29,159.65
VCORE_FT on Bottom Layer "NONET_L-01_P-001" (solid, remove dead copper, pour order 88): 48.215,171.225 49.24,172.25 56.827,172.25 59.765,169.312 59.765,162.275 60.615,161.425 60.765,161.425 60.765,160.725 60.34,160.3 58.49,160.3 57.39,161.4 49.39,161.4 48.765,162.025 48.765,162.225 49.065,162.525 49.065,162.575 57.09,162.575 57.865,163.35 57.865,168.845 55.36,171.35 51.89,171.35 51.065,170.525 48.515,170.525 48.215,170.825
1V8 on Bottom Layer "1V8_L06_P080" (solid, remove dead copper, pour order 80): 209.5,156.725 210.175,156.05 212.9,156.05 213.55,156.7 213.55,157.125 214.55,158.125 231.05,158.125 231.75,158.825 231.75,159.625 231.075,160.3 210.475,160.3 209.5,159.325
5V on Bottom Layer "NONET_L-01_P-001" (solid, remove dead copper, pour order 79): 10.6,90.773 13.902,90.773 15.675,89 15.675,86.675 14.95,85.95 14.925,85.975 12,85.975 10.6,87.375
NetC186_2 on Bottom Layer "C186" (solid, pour order 70): 92.649,190.199 91.6,189.15 89.325,189.15 84.816,193.659 84.816,193.777 80.577,193.777 76.225,189.425 74.1,189.425 72.649,190.876 72.649,193.299 75.95,196.6 89.525,196.6 92.649,193.476
NetC346_2 on Top Layer "C346" (solid, pour order 30): 195.217,192.778 200.457,198.017 216.925,198.017 218.4,196.542 218.4,188.129 217.239,186.967 215.675,186.967 212.625,190.017 202.925,190.017 201.036,188.129 195.722,188.129 195.217,188.634
NetC346_2 on Top Layer "NETC346_2_L01_P101" (solid, remove dead copper, pour order 101): 193.625,187.017 200.522,187.017 203.022,189.518 212.71,189.518 215.785,186.442 218.3,186.442 219.883,188.026 219.883,199.968 196.15,199.968 196.15,193.759 192.778,190.387 192.778,187.865
GND on Top Layer "GND_U5" (solid, remove dead copper, pour order 12): 6.7,78.95 3.7,78.95 3.7,77.25 4.33,76.62 9.67,76.62 13.05,80 13.05,81.653 10.083,81.653 9.275,82.461 9.275,83.25 7.642,83.25 7.642,81.783 4.875,81.783 4.875,81.167 7.45,81.167 7.45,80.58 6.7,80.58
GND on Top Layer "GND_1_TOP" (solid, remove dead copper, pour order 93): 85.298,170.875 88.686,170.875 91.819,174.008 91.819,181.606 89.425,184 85.298,184
5V_T on Top Layer "5V_T_L01_P013" (solid, remove dead copper, pour order 13): 85.994,78.574 85.994,77.406 88.625,74.775 103.8,74.775 104.7,75.675 104.7,76.663 104.188,77.175 98.548,77.175 97.497,78.226 96.4,79.323 96.4,82.407 95.929,82.878 93.734,82.878 90.298,82.878
GND on Top Layer "GND_L01_P067" (solid, remove dead copper, pour order 67): 1.642,116.225 0,114.583 0,111.225 0.9,110.325 26.35,110.325 27.7,111.675 27.7,115.617 27.092,116.225
5V_S on Top Layer "5V_S_L01_P049" (solid, pour order 49): 202.312,157.95 205.443,157.95 205.443,162.025 204.843,162.625 202.822,162.625 202.32,162.123
GND on Top Layer "GND_1_TOP" (solid, pour order 43): 85.975,176.675 85.7,176.4 85.7,175.775 86.45,175.025 86.45,172.162 84.631,172.162 84.229,172.564 84.229,173.95 81.24,173.95 79.609,175.581 79.609,177.184 78.925,177.868 78.925,182.808 80.117,184 85.525,184 85.975,183.55
V+ on Top Layer "NONET_L-01_P-001" (solid, remove dead copper, pour order 5): 4.142,158.341 3.961,158.522 3.136,158.522 2.4,157.787 2.4,155.42 2.524,155.296 3.384,155.296 4.142,156.054
3V3 on Top Layer "3V3_L01_P051" (solid, pour order 51): 206.122,156.75 209.253,156.75 209.253,159.697 208.775,160.175 206.575,160.175 206.128,159.728
3V3 on INT2_SIG "3V3_L03_P115" (solid, remove dead copper, pour order 115): -0.454,67.575 24.206,67.575 24.014,0 161.6,0 161.6,11.095 158.7,11.095 158.281,10.676 158.281,7.004 157.547,6.27 150.506,6.27 147.75,3.515 96.883,3.515 92.013,8.385 70.887,8.385 68.342,5.84 57.043,5.84 57.043,22.125 65.28,22.125 69.005,18.4 80.4,18.4 87.4,25.4 87.4,28.653 92.847,34.1 109.7,34.1 110.249,34.649 110.249,35.306 109.636,35.919 90.111,35.919 85.3,31.108 85.3,28.784 80.72,24.203 70.33,24.203 61.659,32.874 61.659,83.069 60.428,84.3 56.19,84.3 50.89,89.6 50.89,129.18 130.4,129.18 130.4,114.85 139.002,106.248 173.213,106.248 191.166,124.2 213.142,124.2 219.662,117.679 219.1,117.117 219.1,90.298 236.098,73.3 249.919,73.3 249.779,199.889 0.111,199.889 0,200
M2B_3V3 on INT2_SIG "M2B_3V3_L03_P103" (solid, remove dead copper, pour order 103): 144.188,21.112 145.7,19.6 145.7,17.5 152.675,10.525 155.876,10.525 155.876,10.524 156.5,9.9 156.5,8.1 152.15,3.75 144.15,3.75 143.9,4 143.6,4.3 143.6,21.112
5V on INT2_SIG "NONET_L-01_P-001" (solid, remove dead copper, pour order 102): 0,83.36 5.699,83.36 11.746,89.408 15.467,89.408 17.575,87.3 17.575,67.575 14.627,64.627 14.627,56.825 0,56.825
USB1_VBUS on INT2_SIG "USB1_VBUS_L03_P032" (solid, remove dead copper, pour order 32): 131.45,195.189 133.285,197.024 139.733,197.024 142.62,194.137 142.62,189.283 143.062,188.841 143.062,185.467 142.62,185.025 137.355,185.025 131.45,190.93
USB4_5V on INT2_SIG "USB4_5V_L03_P010" (solid, remove dead copper, pour order 10): 110.2,156.9 110.798,156.302 114.081,156.302 120.2,162.421 120.2,175.625 118.1,177.725 118.1,187.9 116.6,189.4 114.964,189.4 114.721,189.157 114.721,187.733 115.913,186.541 115.913,176.636 117.039,175.51 117.039,163.482 116.408,162.852 114.013,162.852 110.2,159.039
USB5_5V on INT2_SIG "USB5_5V_L03_P089" (solid, remove dead copper, pour order 89): 109.697,166.586 109.697,164.704 110.626,163.775 114.64,163.775 115.32,164.454 115.32,187.171 114.721,187.77 114.721,189.226 115.086,189.591 115.086,190.595 114.784,190.898 114.059,190.898 111.2,188.039 111.2,185.705 110.052,184.557 110.052,182.074 111.5,180.625 111.5,176.741 108.795,174.036 108.795,167.213
NetC330_2 on INT2_SIG "NETC330_2_L03_P085" (solid, remove dead copper, pour order 85): 94.515,200 94.515,185.11 95.625,184 110.95,184 112.14,185.19 112.14,200
3V3_UHUB on INT2_SIG "3V3_UHUB" (solid, pour order 71): 94.618,165.545 94.618,160.6 99.711,155.507 104.407,155.507 104.905,156.005 104.905,164.921 103.666,166.16 95.232,166.16
5V on INT2_SIG "5V_L03_P097" (solid, remove dead copper, pour order 97): 29.076,76.367 29.444,76 34.793,76 35.502,76.71 35.502,78.986 35.051,79.437 31.638,79.437 29.076,76.875
1V8 on INT3_SIG "1V8_L04_P114" (solid, remove dead copper, pour order 114): 72.935,200.099 0.035,200.099 0.035,0.099 250.035,0.099 250.135,0.199 250.035,200.099
5V_S on INT3_SIG "5V_S_L04_P105" (solid, remove dead copper, pour order 105): 36.85,75.106 47.1,64.856 47.1,57.914 52.201,52.813 87.664,52.813 104.583,35.894 166.519,35.894 170.702,40.077 174.946,40.077 179.129,35.894 179.129,32.055 208.935,32.055 215.48,38.6 226.903,38.6 237.528,49.225 237.528,65.728 246.395,74.595 246.395,94.88 242.1,99.175 241.05,99.175 240.725,98.85 240.725,95.025 242.65,93.1 242.65,82.5 239.75,79.6 239.75,77.122 229.5,66.872 229.5,48.625 226.775,45.9 216.125,45.9 213.945,48.08 180.12,48.08 179.129,47.089 129.279,47.089 110.704,65.665 54.085,65.665 40.75,79 36.85,79
12V on INT3_SIG "12V_L04_P058" (solid, remove dead copper, pour order 58): 179.05,35.795 175.09,39.755 170.924,39.755 162.741,31.572 52.483,31.572 39.99,44.065 39.99,63.868 32.188,71.67 17.345,71.67 16.9,71.225 16.9,70.36 18.763,68.498 27.098,68.498 35.037,60.558 35.037,38.323 45.745,27.615 48.034,27.615 51.21,24.439 178.82,24.439 179.05,24.669
5V_S on INT3_SIG "5V_S_L04_P104" (solid, pour order 104): 41,75.25 42.623,76.873 42.623,102.852 36.925,108.55 29.975,108.55 29.575,108.15 29.575,103.845 30.15,103.27 35.965,103.27 36.925,102.31 36.925,77.125 38.8,75.25
5V_S on INT3_SIG "5V_S_L04_P106" (solid, remove dead copper, pour order 106): 75.938,157.952 76.341,157.549 78.012,157.549 81.495,154.066 84.591,150.97 88.982,150.97 96.253,143.7 113.577,143.7 127.426,157.549 126.127,158.849 124.798,158.849 111.86,145.911 97.089,145.911 90.6,152.4 84.978,152.4 78.746,158.632 76.195,158.632 75.938,158.375
3V3 on INT3_SIG "3V3_L04_P031" (solid, remove dead copper, pour order 31): 31.3,98.824 30.067,98.824 29.3,98.056 29.3,90.973 31.657,88.617 31.657,87.447 31.06,86.85 26.269,86.85 19.215,93.903 19.215,95.475 20.587,96.846 27.079,96.846 27.448,97.215 27.448,98.824 29.318,100.694 31.149,100.694 32.014,99.829
USB_3_VBUS on INT3_SIG "USB_3_VBUS_L04_P098" (solid, remove dead copper, pour order 98): 119.809,196.024 125.247,196.024 126.994,194.276 126.994,190.598 124.746,188.35 119.492,188.35 118.517,189.324 118.517,191.081 119.216,191.78 121.1,191.78 121.1,192.976 120.063,194.013 119.265,194.013 118.75,194.529 118.75,194.965
VIN on INT3_SIG "VIN_L04_P109" (solid, remove dead copper, pour order 109): 14.734,147.696 39.696,147.696 40.4,148.4 66.511,148.4 69.211,145.7 76.588,145.7 79.005,143.282 79.005,137.54 80.745,135.8 169.725,135.8 189.825,155.9 198.189,155.9 204.879,162.59 204.879,165.621 203.705,166.795 203.343,166.795 202.8,166.253 202.8,164.015 197.285,158.5 187.6,158.5 170.3,141.2 85.2,141.2 78,148.4 70.399,148.4 67.499,151.3 40.6,151.3 39.5,150.2 16.025,150.2 14.475,151.75 14.475,155.5 14.24,155.735 10.235,155.735 8.802,154.302 8.802,148.211 10.413,146.6 13.638,146.6
5V_S on INT3_SIG "5V_S_L04_P107" (solid, remove dead copper, pour order 107): 156.925,174.202 161.39,169.737 209.963,169.737 217.181,162.519 222.974,162.519 243.3,142.193 243.3,112.536 246.395,109.441 246.395,93.1 242.65,93.1 235.867,99.883 235.867,141.733 220.4,157.2 203.151,157.2 202.2,158.151 202.2,160.093 203.107,161 204.226,161 205.4,162.174 205.4,165.824 204.024,167.2 202.7,167.2 201.6,166.1 157.635,166.1 153.486,170.249 153.486,173.216 154.472,174.202
5V_S on INT3_SIG "5V_S_L04_P077" (solid, remove dead copper, pour order 77): 154.155,181.616 154.344,181.805 154.857,181.805 159.198,177.464 159.198,177.116 158.781,176.7 157.507,176.7 156.925,176.118 156.925,171.945 154.994,170.013 144.222,170.013 127.442,170.013 127.18,169.751 127.18,162.882 126.314,162.016 126.314,159.799 127.444,158.669 127.444,157.567 127.077,157.2 123.9,157.2 123.55,157.55 123.55,175.601 125.104,177.155 126.242,177.155 128.322,175.075 143.725,175.075 146.651,172.149 151.861,172.149 155.235,175.524 155.235,179.461 154.155,180.541
NetC101_2 on INT3_SIG "NETC101_2_L04_P081" (solid, remove dead copper, pour order 81): 127.353,200 127.353,194.428 127.742,194.039 129.966,194.039 130.25,194.323 130.25,195.116 131.134,196 134.85,196 136,194.85 136,194.408 136.369,194.039 140.319,194.039 141.613,195.333 141.613,200
1V0_ETH2 on INT3_SIG "1V0_ETH2" (solid, pour order 100): 78.625,175.325 82.675,171.275 83.363,171.275 84.311,172.224 86.699,172.224 87.475,173 87.475,174.425 82.925,178.975 81.725,178.975 78.625,175.875
GND on INT4_GND (split plane): 249.49,0.51 0.51,0.51 0.51,18.55 16.125,18.55 21.25,23.675 28.55,23.675 31.55,26.675 31.55,43.45 31.55,60.325 28.3,63.575 24.32,63.575 17.395,56.65 0.51,56.65 0.51,85.963 14.793,85.963 14.842,85.972 14.883,86 15.523,86.64 15.551,86.681 15.56,86.73 15.56,88.862 15.551,88.911 15.523,88.952 11.71,92.765 11.668,92.793 11.62,92.802 10.753,92.802 5.322,98.234 5.322,116.106 5.312,116.155 5.284,116.196 2.56,118.92 2.56,124.386 4.365,126.191 4.393,126.232 4.394,126.24 4.402,126.281 4.402,137.978 5.632,139.208 19.786,139.208 19.835,139.218 19.876,139.245 20.582,139.952 20.61,139.993 20.62,140.042 20.62,141.543 20.61,141.592 20.582,141.633 18.739,143.476 18.698,143.504 18.649,143.513 0.51,143.513 0.51,199.49 232.865,199.49 232.865,198.7 232.874,198.6 232.903,198.505 232.951,198.416 233.014,198.339 233.091,198.276 233.18,198.228 233.275,198.199 233.375,198.19 237.875,198.19 237.975,198.199 238.07,198.228 238.159,198.276 238.236,198.339 238.299,198.416 238.347,198.505 238.376,198.6 238.385,198.7 238.385,199.49 249.49,199.49
no net on INT4_GND (split plane): 0.51,38.274 19.349,38.274
5V_ISO1 on INT4_GND (split plane): 28.522,60.221 28.522,45.248 27.499,44.225 23.825,44.225 19.35,39.75 0.51,39.75 0.51,53.351 17.445,53.351 25.139,61.045 27.698,61.045
5V_ISO2 on INT4_GND (split plane): 28.522,41.845 28.522,26.772 27.475,25.725 21.5,25.725 16.15,20.375 0.51,20.375 0.51,34.975 17.445,34.975 25.139,42.669 27.698,42.669
5V on INT4_GND (split plane): 20.365,141.49 20.365,140.095 19.733,139.463 5.58,139.463 5.531,139.453 5.489,139.426 4.185,138.121 4.157,138.08 4.148,138.031 4.148,126.334 2.343,124.529 2.315,124.488 2.305,124.439 2.305,118.867 2.315,118.818 2.343,118.777 5.067,116.053 5.067,98.181 5.076,98.132 5.104,98.091 10.61,92.585 10.651,92.557 10.7,92.548 11.567,92.548 15.305,88.809 15.305,86.783 14.74,86.218 0.51,86.218 0.51,143.258 18.596,143.258
1V8_ETH2 on INT4_GND (split plane): 87.018,179.552 87.018,178.873 86.18,178.035 86.152,177.994 86.143,177.945 86.143,175.374 83.796,173.027 80.088,173.027 80.039,173.018 79.998,172.99 77.793,170.786 69.47,170.786 67.227,173.028 67.227,173.522 68.003,174.298 73.656,174.298 73.704,174.307 73.746,174.335 79.258,179.848 86.722,179.848
GND on INT1_GND (split plane): 249.49,0.51 0.51,0.51 0.51,18.55 16.125,18.55 21.25,23.675 28.55,23.675 31.55,26.675 31.55,43.45 31.55,60.325 28.3,63.575 24.32,63.575 17.395,56.65 0.51,56.65 0.51,199.49 232.865,199.49 232.865,198.7 232.874,198.6 232.903,198.505 232.951,198.416 233.014,198.339 233.091,198.276 233.18,198.228 233.275,198.199 233.375,198.19 237.875,198.19 237.975,198.199 238.07,198.228 238.159,198.276 238.236,198.339 238.299,198.416 238.347,198.505 238.376,198.6 238.385,198.7 238.385,199.49 249.49,199.49
GND_ISO2 on INT1_GND (split plane): 28.522,41.845 28.522,26.772 27.475,25.725 21.5,25.725 16.15,20.375 0.51,20.375 0.51,34.975 17.445,34.975 25.139,42.669 27.698,42.669
no net on INT1_GND (split plane): 0.51,38.274 19.349,38.274
GND_ISO1 on INT1_GND (split plane): 28.522,60.221 28.522,45.248 27.499,44.225 23.825,44.225 19.35,39.75 0.51,39.75 0.51,53.351 17.445,53.351 25.139,61.045 27.698,61.045

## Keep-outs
Keep-Out Layer:
  lines w0.05: 0,0 0,200 250,200 250,0 0,0 ; 0,0 0,0 ; 0,18.55 0,20.375 16.15,20.375 21.5,25.725 27.475,25.725 28.522,26.772 28.522,41.845 27.698,42.669 25.139,42.669 17.445,34.975 0,34.975 0,38.274 19.349,38.274 24.525,43.45 31.55,43.45 31.55,26.675 28.55,23.675 21.25,23.675 16.125,18.55 0,18.55 ; 0,38.35 19.3,38.35 24.5,43.55 31.55,43.55 31.55,60.325 28.3,63.575 24.32,63.575 17.395,56.65 0,56.65 0,53.351 17.445,53.351 25.139,61.045 27.698,61.045 28.522,60.221 28.522,45.248 27.499,44.225 23.825,44.225 19.35,39.75 0,39.75 0,38.35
